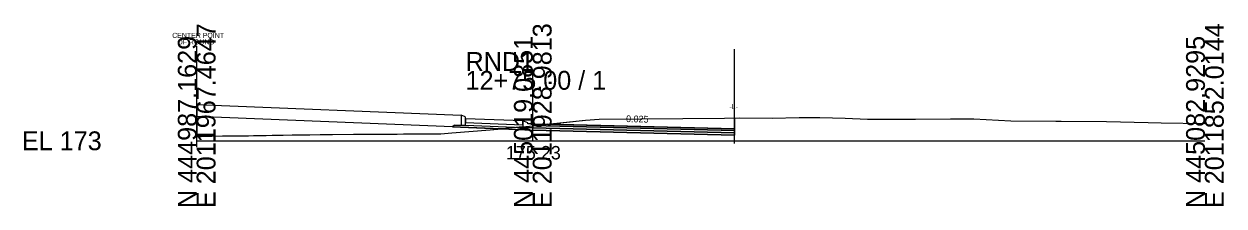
# Model space of a CAD drawing. Extents: x -26 to 153, y -10 to 6017.
# Drawn here: x -25.7 to 152.8, y 5490.3 to 5517.4 of the extents above; entities that cross this region are included whole.
import ezdxf

# ---------------------------------------------------------------- set-up
doc = ezdxf.new("R2010")
doc.units = 0
for name, color, linetype in [('Exist Cross Section Cell', 7, 'Continuous'), ('Exist XS Ground Line', 7, 'Continuous'), ('Prop CMT Conc Surface', 7, 'Continuous'), ('Prop CMT Concrete Structures', 7, 'Continuous'), ('Prop CMT Pvmt Course 1', 7, 'Continuous'), ('Prop CMT Pvmt Course 1 CG', 7, 'Continuous'), ('Prop CMT Pvmt Course 2', 7, 'Continuous'), ('Prop CMT Pvmt Course 3', 7, 'Continuous'), ('Prop CMT Pvmt Surface', 7, 'Continuous'), ('Prop CMT Shear Line', 7, 'Continuous'), ('Prop CMT Shear Line Text', 7, 'Continuous'), ('Prop CMT Slope Grass', 7, 'Continuous'), ('Prop CMT Subgrade Earthwork', 7, 'Continuous'), ('Prop XS Earthwork Shape', 7, 'Continuous'), ('Prop XS SE Text', 7, 'Continuous'), ('Scratch_Level_1', 7, 'Continuous')]:
    doc.layers.add(name, color=color, linetype=linetype)

msp = doc.modelspace()

# ---------------------------------------------------------------- linework, layer by layer
at = {"layer": 'Exist Cross Section Cell'}
for p, q in [((50, 5500), (50, 5510.4)), ((0, 5500), (50, 5500)), ((50, 5500), (150, 5500))]:
    msp.add_line(p, q, dxfattribs=at)
at = {"layer": 'Exist XS Ground Line'}
msp.add_lwpolyline([(0, 5500.62), (0.66, 5500.63), (3.83, 5500.73), (4.14, 5500.74), (4.51, 5500.75), (5.91, 5500.75), (7.08, 5500.76), (7.7, 5500.76), (8.44, 5500.77), (9.47, 5500.79), (10.32, 5500.81), (11.24, 5500.83), (12.35, 5500.85), (12.85, 5500.86), (14.21, 5500.89), (16.82, 5500.91), (18.35, 5500.93), (20.21, 5500.96), (23.32, 5500.99), (24.11, 5501), (25.44, 5501), (26.58, 5501), (28.04, 5501), (28.98, 5501.01), (29.81, 5501.01), (30.78, 5501.02), (31.92, 5501.03), (32.6, 5501.03), (33.2, 5501.04), (34.31, 5501.05), (35.53, 5501.05), (36.33, 5501.05), (37.98, 5501.21), (43.64, 5501.65), (45.95, 5501.84), (46.42, 5501.88), (46.94, 5501.91), (50, 5502.23), (57.87, 5503.07), (59.89, 5503.24), (78.51, 5503.39), (80.81, 5503.43), (85.62, 5503.37), (89.61, 5503.46), (92.72, 5503.47), (96.48, 5503.38), (99.82, 5503.24), (102.6, 5503.22), (106.93, 5503.2), (112.14, 5503.29), (114.03, 5503.28), (115.6, 5503.27), (121.13, 5502.97), (127.81, 5502.91), (128.23, 5502.9), (128.59, 5502.91), (135.34, 5502.86), (141.58, 5502.71), (143.47, 5502.69), (150, 5502.57)], dxfattribs=at)
at = {"layer": 'Prop CMT Conc Surface'}
for points in [[(40, 5503.48), (39.96, 5503.58), (39.85, 5503.63), (39.34, 5503.81)], [(40, 5503.31), (40, 5503.48)], [(50, 5502.52), (49.25, 5502.54), (49.25, 5502.7), (48.5, 5502.95)]]:
    msp.add_lwpolyline(points, dxfattribs=at)
at = {"layer": 'Prop CMT Concrete Structures'}
for points in [[(40, 5503.48), (39.96, 5503.58), (39.85, 5503.63), (39.34, 5503.81)], [(39.34, 5503.81), (39.34, 5502.31)], [(40, 5503.31), (40, 5503.48)], [(40, 5502.31), (40, 5503.31)], [(40, 5503.31), (40, 5502.73)], [(48.5, 5502.95), (40, 5503.29)], [(40, 5502.71), (48.5, 5502.37)], [(50, 5502.52), (49.25, 5502.54), (49.25, 5502.7), (48.5, 5502.95)], [(48.5, 5502.95), (48.5, 5501.97)], [(48.5, 5502.37), (48.5, 5502.95)], [(50, 5501.93), (50, 5502.52)], [(39.34, 5502.31), (40, 5502.31)], [(48.5, 5501.97), (50, 5501.93)]]:
    msp.add_lwpolyline(points, dxfattribs=at)
at = {"layer": 'Prop CMT Pvmt Course 1'}
for points in [[(50, 5502.52), (80, 5501.77)], [(50, 5502.27), (50, 5502.52)], [(80, 5501.52), (50, 5502.27)], [(80, 5501.77), (80, 5501.52)]]:
    msp.add_lwpolyline(points, dxfattribs=at)
msp.add_lwpolyline([(50, 5502.27), (50, 5502.39), (50, 5502.39), (50, 5502.27)], close=True, dxfattribs=at)
at = {"layer": 'Prop CMT Pvmt Course 1 CG'}
for points in [[(50, 5501.6), (50, 5501.93)], [(80, 5500.85), (80, 5501.18)]]:
    msp.add_lwpolyline(points, dxfattribs=at)
at = {"layer": 'Prop CMT Pvmt Course 2'}
for points in [[(50, 5501.93), (50, 5502.27)], [(50, 5502.27), (80, 5501.52)], [(80, 5501.18), (50, 5501.93)], [(80, 5501.52), (80, 5501.18)]]:
    msp.add_lwpolyline(points, dxfattribs=at)
at = {"layer": 'Prop CMT Pvmt Course 3'}
for points in [[(40, 5502.31), (48.5, 5501.97)], [(50, 5501.93), (80, 5501.18)], [(50, 5501.6), (50, 5501.93)], [(80, 5500.85), (50, 5501.6)], [(80, 5501.18), (80, 5500.85)]]:
    msp.add_lwpolyline(points, dxfattribs=at)
at = {"layer": 'Prop CMT Pvmt Surface'}
msp.add_lwpolyline([(50, 5502.52), (80, 5501.77)], dxfattribs=at)
at = {"layer": 'Prop CMT Shear Line'}
for p, q in [((0, 5499.06), (0, 5514.06)), ((80, 5499.59), (80, 5504.6))]:
    msp.add_line(p, q, dxfattribs=at)
at = {"layer": 'Prop CMT Slope Grass'}
for p, q in [((39.34, 5503.79), (0, 5505.37)), ((38.06, 5502.08), (0, 5503.6))]:
    msp.add_line(p, q, dxfattribs=at)
at = {"layer": 'Prop CMT Subgrade Earthwork'}
for p, q in [((0, 5505.37), (0, 5500.62)), ((80, 5500.85), (80, 5503.41)), ((38.34, 5502.35), (38.06, 5502.08))]:
    msp.add_line(p, q, dxfattribs=at)
for points in [[(38.06, 5502.08), (50, 5501.6)], [(38.34, 5502.35), (39.34, 5502.31)], [(50, 5501.6), (80, 5500.85)]]:
    msp.add_lwpolyline(points, dxfattribs=at)
at = {"layer": 'Prop XS Earthwork Shape'}
for points in [[(10.32, 5500.81), (11.24, 5500.83), (12.35, 5500.85), (12.85, 5500.86), (14.21, 5500.89), (16.82, 5500.91), (18.35, 5500.93), (20.21, 5500.96), (23.32, 5500.99), (24.11, 5501), (25.44, 5501), (26.58, 5501), (28.04, 5501), (28.98, 5501.01), (29.81, 5501.01), (30.78, 5501.02), (31.92, 5501.03), (32.6, 5501.03), (33.2, 5501.04), (34.31, 5501.05), (35.53, 5501.05), (36.33, 5501.05), (37.98, 5501.21), (43.64, 5501.65), (45.33, 5501.79), (38.06, 5502.08), (0, 5503.6), (0, 5500.62), (0.66, 5500.63), (3.83, 5500.73), (4.14, 5500.74), (4.51, 5500.75), (5.91, 5500.75), (7.08, 5500.76), (7.7, 5500.76), (8.44, 5500.77), (9.47, 5500.79)], [(80, 5500.85), (80, 5501.77), (52.16, 5502.46), (50, 5502.23), (50, 5501.93), (48.5, 5501.97), (48.5, 5502.07), (46.94, 5501.91), (46.42, 5501.88), (45.95, 5501.84), (45.33, 5501.79), (50, 5501.6)], [(78.51, 5503.39), (80, 5503.41), (80, 5501.77), (52.16, 5502.46), (57.87, 5503.07), (59.89, 5503.24)], [(48.5, 5502.07), (50, 5502.23), (50, 5501.93), (48.5, 5501.97)]]:
    msp.add_lwpolyline(points, close=True, dxfattribs=at)
at = {"layer": 'Scratch_Level_1'}
msp.add_line((80, 5501.55), (80, 5513.62), dxfattribs=at)

# ---------------------------------------------------------------- texts
at = {"layer": 'Exist Cross Section Cell'}
for s, p in [('E 2011967.4647', (2.8, 5490)), ('E 2011928.9813', (52.8, 5490)), ('E 2011852.0144', (152.8, 5490)), ('N 444987.1629', (0, 5490)), ('N 445019.0851', (50, 5490)), ('N 445082.9295', (150, 5490))]:
    msp.add_text(s, height=2.8, rotation=90, dxfattribs=at).set_placement(p)
for s, p in [('RND1', (40, 5510.4)), ('12+75.00 / 1', (40, 5507.6)), ('EL 173', (-26, 5498.6))]:
    msp.add_text(s, height=2.8, dxfattribs=at).set_placement(p)
at = {"layer": 'Exist XS Ground Line'}
msp.add_text('175.23', height=2, dxfattribs=at).set_placement((45.99, 5497.23))
at = {"layer": 'Prop CMT Shear Line Text'}
for s, p in [('CENTER POINT', (-3.64, 5515.31)), ('OF ROUND', (-2.88, 5514.33)), ('-L-', (79.27, 5504.72))]:
    msp.add_text(s, height=0.75, dxfattribs=at).set_placement(p)
at = {"layer": 'Prop XS SE Text'}
msp.add_text('0.025', height=1, rotation=358.5613, dxfattribs=at).set_placement((63.87, 5502.79))

doc.saveas('drawing.dxf')
